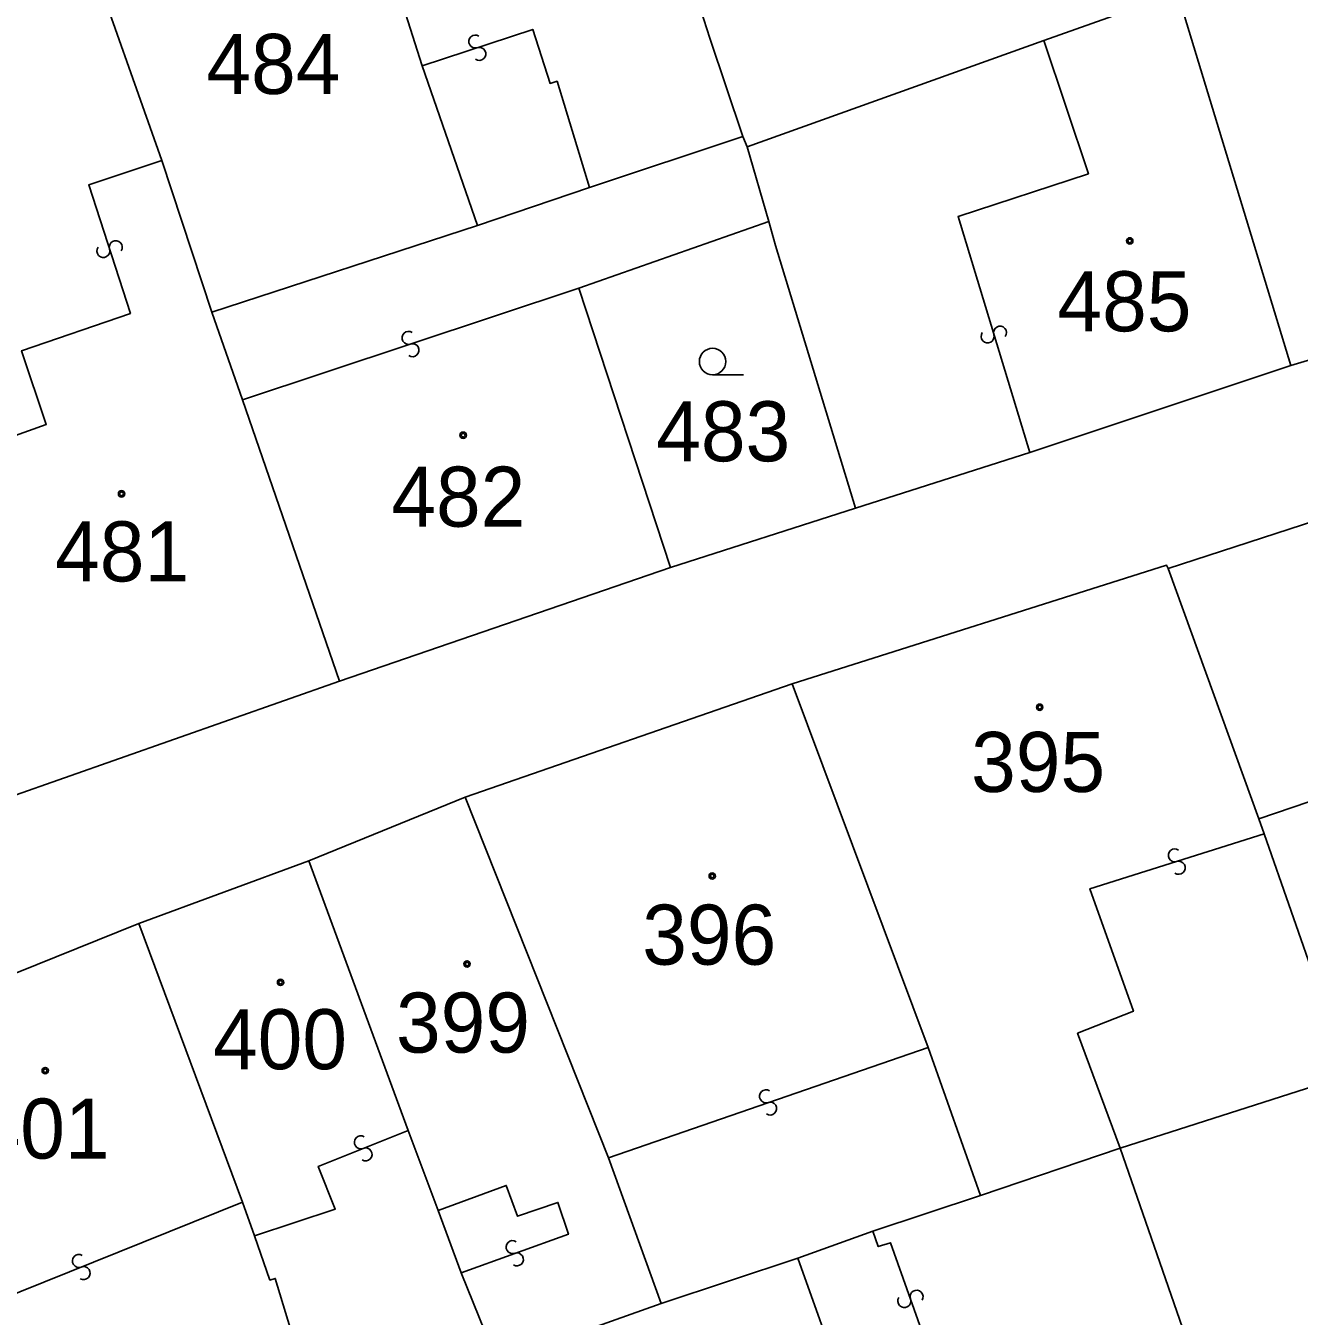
# Model space of a CAD drawing. Extents: x -598233 to -596890, y -1157848 to -1156431.
# Drawn here: x -597220.24 to -597184.2, y -1157463.99 to -1157427.46 of the extents above; entities that cross this region are included whole.
import ezdxf

# ---------------------------------------------------------------- set-up
doc = ezdxf.new("R2010")
doc.units = 0
for name, color, linetype in [('Level 1', 7, 'Continuous'), ('Level 13', 7, 'Continuous'), ('Level 3', 7, 'Continuous'), ('Level 4', 7, 'Continuous'), ('Level 5', 7, 'Continuous'), ('Level 60', 7, 'Continuous')]:
    doc.layers.add(name, color=color, linetype=linetype)

msp = doc.modelspace()

# ---------------------------------------------------------------- linework, layer by layer
at = {"layer": 'Level 1'}
for points in [[(-597209.02, -1157428.59), (-597210.97, -1157422.45)], [(-597218.53, -1157425.21), (-597216.39, -1157431.27)], [(-597187.64, -1157426.53), (-597191.42, -1157427.88)], [(-597184.43, -1157437.08), (-597187.64, -1157426.53)], [(-597199.94, -1157430.59), (-597200.88, -1157427.81), (-597201.05, -1157427.28)], [(-597191.42, -1157427.88), (-597199.82, -1157430.89)], [(-597207.45, -1157433.11), (-597209.02, -1157428.59)], [(-597199.94, -1157430.59), (-597204.28, -1157432.04)], [(-597199.82, -1157430.89), (-597199.94, -1157430.59)], [(-597199.21, -1157433), (-597199.82, -1157430.89)], [(-597216.39, -1157431.27), (-597214.97, -1157435.57)], [(-597204.28, -1157432.04), (-597207.45, -1157433.11)], [(-597204.59, -1157434.89), (-597199.21, -1157433)], [(-597196.75, -1157441.12), (-597199.02, -1157433.68), (-597199.21, -1157433)], [(-597207.45, -1157433.11), (-597214.97, -1157435.57)], [(-597184.43, -1157437.08), (-597171.91, -1157433.32)], [(-597201.99, -1157442.8), (-597204.59, -1157434.89)], [(-597214.11, -1157438.05), (-597214.97, -1157435.57)], [(-597184.43, -1157437.08), (-597191.82, -1157439.54)], [(-597211.36, -1157446.01), (-597214.11, -1157438.05)], [(-597191.82, -1157439.54), (-597196.75, -1157441.12)], [(-597187.9, -1157442.82), (-597179.17, -1157439.98)], [(-597201.99, -1157442.8), (-597196.75, -1157441.12)], [(-597211.36, -1157446.01), (-597201.99, -1157442.8)], [(-597198.55, -1157446.09), (-597187.95, -1157442.73), (-597187.9, -1157442.82)], [(-597187.9, -1157442.82), (-597185.34, -1157449.91)], [(-597220.7, -1157449.3), (-597211.36, -1157446.01)], [(-597198.55, -1157446.09), (-597207.8, -1157449.3)], [(-597198.55, -1157446.09), (-597194.7, -1157456.38)], [(-597212.23, -1157451.1), (-597207.8, -1157449.3)], [(-597207.8, -1157449.3), (-597203.75, -1157459.51)], [(-597185.34, -1157449.91), (-597185.19, -1157450.34)], [(-597185.19, -1157450.34), (-597183.66, -1157454.71)], [(-597217.04, -1157452.87), (-597212.23, -1157451.1)], [(-597209.42, -1157458.73), (-597212.23, -1157451.1)], [(-597226.32, -1157456.61), (-597217.04, -1157452.87)], [(-597217.04, -1157452.87), (-597214.11, -1157460.76)], [(-597194.7, -1157456.38), (-597193.22, -1157460.57)], [(-597189.26, -1157459.23), (-597182.81, -1157457.17)], [(-597208.57, -1157461), (-597209.42, -1157458.73)], [(-597193.22, -1157460.57), (-597189.26, -1157459.23)], [(-597185.66, -1157469.62), (-597189.26, -1157459.23)], [(-597203.75, -1157459.51), (-597202.26, -1157463.63)], [(-597214.11, -1157460.76), (-597213.77, -1157461.72)], [(-597196.26, -1157461.58), (-597193.22, -1157460.57)], [(-597207.92, -1157462.76), (-597208.57, -1157461)], [(-597213.77, -1157461.72), (-597213.33, -1157462.97), (-597213.18, -1157462.92), (-597211.95, -1157466.99)], [(-597198.39, -1157462.35), (-597196.26, -1157461.58)], [(-597202.26, -1157463.63), (-597198.39, -1157462.35)], [(-597197.09, -1157465.97), (-597198.39, -1157462.35)], [(-597206.9, -1157465.28), (-597207.92, -1157462.76)], [(-597206.9, -1157465.28), (-597202.26, -1157463.63)]]:
    msp.add_lwpolyline(points, dxfattribs=at)
at = {"layer": 'Level 13'}
for centre, start, end in [((-597207.516, -1157427.904), 55.5877, 287.6857), ((-597207.403, -1157428.255), 235.3733, 107.9633), ((-597218.045, -1157433.836), 145.1197, 17.7097), ((-597217.694, -1157433.725), 325.3342, 197.4322), ((-597192.663, -1157436.148), 324.2764, 196.3744), ((-597209.406, -1157436.294), 55.7354, 287.8334), ((-597193.016, -1157436.253), 144.0619, 16.6519), ((-597209.293, -1157436.645), 235.521, 108.111), ((-597187.714, -1157450.944), 54.826, 286.924), ((-597187.606, -1157451.296), 234.6115, 107.2015), ((-597199.289, -1157457.765), 56.451, 288.549), ((-597199.171, -1157458.114), 236.2365, 108.8265), ((-597210.757, -1157459.068), 59.2519, 291.3499), ((-597210.622, -1157459.411), 239.0374, 111.6274), ((-597206.461, -1157462.036), 56.8837, 289.4737), ((-597218.738, -1157462.429), 59.0787, 291.6687), ((-597206.339, -1157462.384), 237.0982, 109.1962), ((-597218.603, -1157462.772), 239.2932, 111.3912), ((-597195.026, -1157463.44), 326.8785, 198.9765), ((-597195.374, -1157463.561), 146.6641, 19.2541)]:
    msp.add_arc(centre, 0.184, start, end, dxfattribs=at)
at = {"layer": 'Level 3'}
for points in [[(-597209.02, -1157428.59), (-597205.89, -1157427.56), (-597205.4, -1157429.09), (-597205.2, -1157429.03), (-597204.28, -1157432.04)], [(-597191.42, -1157427.88), (-597190.16, -1157431.65), (-597193.85, -1157432.86), (-597191.82, -1157439.54)], [(-597216.39, -1157431.27), (-597218.46, -1157431.96), (-597217.28, -1157435.6), (-597220.36, -1157436.66), (-597219.66, -1157438.75), (-597222.17, -1157439.64), (-597222.96, -1157437.29), (-597224.71, -1157437.79)], [(-597214.11, -1157438.05), (-597204.59, -1157434.89)], [(-597185.34, -1157449.91), (-597180.65, -1157448.32), (-597178.97, -1157453.23), (-597183.66, -1157454.71)], [(-597189.26, -1157459.23), (-597190.47, -1157455.98), (-597188.89, -1157455.36), (-597190.12, -1157451.89), (-597185.19, -1157450.34)], [(-597203.75, -1157459.51), (-597194.7, -1157456.38)], [(-597213.77, -1157461.72), (-597211.48, -1157460.96), (-597211.96, -1157459.75), (-597209.42, -1157458.73)], [(-597208.57, -1157461), (-597206.64, -1157460.29), (-597206.32, -1157461.16), (-597205.18, -1157460.77), (-597204.88, -1157461.67), (-597207.92, -1157462.76)], [(-597214.11, -1157460.76), (-597223.23, -1157464.43)], [(-597196.26, -1157461.58), (-597196.11, -1157462.02), (-597195.76, -1157461.91), (-597194.63, -1157465.1), (-597197.09, -1157465.97)]]:
    msp.add_lwpolyline(points, dxfattribs=at)
at = {"layer": 'Level 5'}
msp.add_line((-597200.8, -1157437.34), (-597199.925, -1157437.34), dxfattribs=at)
for centre, radius in [((-597188.99, -1157433.55), 0.09), ((-597188.99, -1157433.55), 0.0521), ((-597200.8, -1157436.965), 0.375), ((-597207.86, -1157439.05), 0.09), ((-597207.86, -1157439.05), 0.0521), ((-597217.53, -1157440.71), 0.09), ((-597217.53, -1157440.71), 0.0521), ((-597191.54, -1157446.75), 0.09), ((-597191.54, -1157446.75), 0.0521), ((-597200.81, -1157451.53), 0.09), ((-597200.81, -1157451.53), 0.0521), ((-597207.75, -1157454.02), 0.09), ((-597207.75, -1157454.02), 0.0521), ((-597213.03, -1157454.54), 0.09), ((-597213.03, -1157454.54), 0.0521), ((-597219.69, -1157457.04), 0.09), ((-597219.69, -1157457.04), 0.0521)]:
    msp.add_circle(centre, radius, dxfattribs=at)
at = {"layer": 'Level 60'}
for points in [[(-597199.82, -1157430.89), (-597199.94, -1157430.59), (-597200.88, -1157427.81), (-597201.05, -1157427.28), (-597203.65, -1157419.05), (-597191.17, -1157415.43), (-597188.96, -1157422.62), (-597188.67, -1157423.58), (-597187.64, -1157426.53), (-597191.42, -1157427.88)], [(-597211.25, -1157421.55), (-597203.65, -1157419.05), (-597201.05, -1157427.28), (-597200.88, -1157427.81), (-597199.94, -1157430.59), (-597204.28, -1157432.04), (-597207.45, -1157433.11), (-597209.02, -1157428.59), (-597210.97, -1157422.45)], [(-597207.45, -1157433.11), (-597214.97, -1157435.57), (-597216.39, -1157431.27), (-597218.53, -1157425.21), (-597218.59, -1157425.04), (-597218.59, -1157424), (-597215.9, -1157423), (-597211.31, -1157421.34), (-597211.25, -1157421.55), (-597210.97, -1157422.45), (-597209.02, -1157428.59)], [(-597175.71, -1157422.58), (-597175.62, -1157422.72), (-597175.41, -1157422.68), (-597174.53, -1157425.34), (-597171.91, -1157433.32), (-597184.43, -1157437.08), (-597187.64, -1157426.53), (-597183.11, -1157425.03)], [(-597214.11, -1157438.05), (-597211.36, -1157446.01), (-597220.7, -1157449.3), (-597223.83, -1157440.34), (-597224.71, -1157437.79), (-597225.62, -1157435.2), (-597226.2, -1157433.62), (-597226.34, -1157433.24), (-597228.02, -1157428.32), (-597224.45, -1157427.15), (-597218.53, -1157425.21), (-597216.39, -1157431.27), (-597214.97, -1157435.57)], [(-597187.64, -1157426.53), (-597184.43, -1157437.08), (-597191.82, -1157439.54), (-597196.75, -1157441.12), (-597199.02, -1157433.68), (-597199.21, -1157433), (-597199.82, -1157430.89), (-597191.42, -1157427.88)], [(-597214.97, -1157435.57), (-597207.45, -1157433.11), (-597204.28, -1157432.04), (-597199.94, -1157430.59), (-597199.82, -1157430.89), (-597199.21, -1157433), (-597204.59, -1157434.89), (-597201.99, -1157442.8), (-597211.36, -1157446.01), (-597214.11, -1157438.05)], [(-597196.75, -1157441.12), (-597201.99, -1157442.8), (-597204.59, -1157434.89), (-597199.21, -1157433), (-597199.02, -1157433.68)], [(-597187.9, -1157442.82), (-597179.17, -1157439.98), (-597176.6, -1157447.81), (-597174.47, -1157454.12), (-597178.16, -1157455.47), (-597182.81, -1157457.17), (-597183.66, -1157454.71), (-597185.19, -1157450.34), (-597185.34, -1157449.91)], [(-597198.55, -1157446.09), (-597187.95, -1157442.73), (-597187.9, -1157442.82), (-597185.34, -1157449.91), (-597185.19, -1157450.34), (-597183.66, -1157454.71), (-597182.81, -1157457.17), (-597189.26, -1157459.23), (-597193.22, -1157460.57), (-597194.7, -1157456.38)], [(-597207.8, -1157449.3), (-597198.55, -1157446.09), (-597194.7, -1157456.38), (-597193.22, -1157460.57), (-597196.26, -1157461.58), (-597198.39, -1157462.35), (-597202.26, -1157463.63), (-597203.75, -1157459.51)], [(-597212.23, -1157451.1), (-597207.8, -1157449.3), (-597203.75, -1157459.51), (-597202.26, -1157463.63), (-597206.9, -1157465.28), (-597207.92, -1157462.76), (-597208.57, -1157461), (-597209.42, -1157458.73)], [(-597217.04, -1157452.87), (-597212.23, -1157451.1), (-597209.42, -1157458.73), (-597208.57, -1157461), (-597207.92, -1157462.76), (-597206.9, -1157465.28), (-597211.95, -1157466.99), (-597213.18, -1157462.92), (-597213.33, -1157462.97), (-597213.77, -1157461.72), (-597214.11, -1157460.76)], [(-597174.47, -1157454.12), (-597167.97, -1157452), (-597167.86, -1157452.48), (-597165.94, -1157451.98), (-597167.38, -1157455.2), (-597171.74, -1157464.58), (-597171.83, -1157464.77), (-597172.57, -1157466.28), (-597185.27, -1157470.89), (-597185.66, -1157469.62), (-597189.26, -1157459.23), (-597182.81, -1157457.17), (-597178.16, -1157455.47)], [(-597218.09, -1157469.47), (-597220.78, -1157470.63), (-597222.29, -1157466.8), (-597223.23, -1157464.43), (-597226.32, -1157456.61), (-597217.04, -1157452.87), (-597214.11, -1157460.76), (-597213.77, -1157461.72), (-597213.33, -1157462.97), (-597213.18, -1157462.92), (-597211.95, -1157466.99)], [(-597198.39, -1157462.35), (-597196.26, -1157461.58), (-597193.22, -1157460.57), (-597189.26, -1157459.23), (-597185.66, -1157469.62), (-597185.27, -1157470.89), (-597194.18, -1157474.04), (-597194.61, -1157472.84), (-597197.09, -1157465.97)], [(-597212.94, -1157481.06), (-597213.59, -1157479.53), (-597196.52, -1157473.4), (-597198.55, -1157467.13), (-597205.46, -1157469.65), (-597206.19, -1157467.6), (-597206.9, -1157465.28), (-597202.26, -1157463.63), (-597198.39, -1157462.35), (-597197.09, -1157465.97), (-597194.61, -1157472.84), (-597194.18, -1157474.04)]]:
    msp.add_lwpolyline(points, close=True, dxfattribs=at)
for points in [[(-597277.51, -1157474.7), (-597264.71, -1157468.87), (-597256.77, -1157465.25), (-597255.6, -1157463.18), (-597254.01, -1157462.52), (-597244.9, -1157458.69), (-597244.71, -1157459.06), (-597235.01, -1157454.93), (-597235.14, -1157454.63), (-597228.97, -1157452.45), (-597229.02, -1157452.35), (-597220.7, -1157449.3), (-597211.36, -1157446.01), (-597201.99, -1157442.8), (-597196.75, -1157441.12), (-597191.82, -1157439.54), (-597184.43, -1157437.08), (-597171.91, -1157433.32)], [(-597179.17, -1157439.98), (-597187.9, -1157442.82), (-597187.95, -1157442.73), (-597198.55, -1157446.09), (-597207.8, -1157449.3), (-597212.23, -1157451.1), (-597217.04, -1157452.87), (-597226.32, -1157456.61), (-597234.49, -1157460.06), (-597235.21, -1157460.39), (-597240, -1157462.36), (-597240.89, -1157462.76), (-597240.97, -1157462.59), (-597244.58, -1157464.14), (-597253.64, -1157468.1), (-597262.41, -1157471.57), (-597263.77, -1157472.19), (-597264.04, -1157471.7), (-597271.88, -1157475.05)]]:
    msp.add_lwpolyline(points, dxfattribs=at)

# ---------------------------------------------------------------- texts
at = {"layer": 'Level 4'}
for s, p in [('484', (-597215.128, -1157429.39)), ('485', (-597191.039, -1157436.11)), ('483', (-597202.395, -1157439.79)), ('482', (-597209.893, -1157441.64)), ('481', (-597219.411, -1157443.19)), ('395', (-597193.482, -1157449.15)), ('396', (-597202.791, -1157454.04)), ('399', (-597209.761, -1157456.53)), ('400', (-597214.941, -1157457)), ('401', (-597221.661, -1157459.53))]:
    msp.add_text(s, height=1.7, dxfattribs=at).set_placement(p)

doc.saveas('drawing.dxf')
